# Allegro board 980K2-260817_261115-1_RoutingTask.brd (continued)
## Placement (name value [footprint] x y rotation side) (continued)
NOREF#2374  -  []  249.52 212.86 90 top
NOREF#2375  -  []  227.43 218.27 90 top
NOREF#2376  -  []  239.27 211.67 0 top
NOREF#2377  -  []  144.04 245.96 0 top
NOREF#2378  -  []  188.78 222.65 0 top
NOREF#2379  -  []  181.85 306.46 0 top
NOREF#2380  -  []  143.49 253.03 90 top
NOREF#2381  -  []  269.12 240.3 90 top
NOREF#2382  -  []  211.05 292.28 90 top
NOREF#2383  -  []  187.43 224.11 0 top
NOREF#2384  -  []  157.04 184.35 0 top
NOREF#2385  -  []  221.03 207.69 90 top
NOREF#2386  -  []  197.25 256.75 0 top
NOREF#2387  -  []  216.38 264.09 90 top
NOREF#2388  -  []  271.18 179.15 0 top
NOREF#2389  -  []  159.27 204.78 90 top
NOREF#2390  -  []  139.73 178.35 0 top
NOREF#2391  -  []  159.4 205.9 0 top
NOREF#2392  -  []  268.35 217.95 90 top
NOREF#2393  -  []  230.6 233.69 90 top
NOREF#2394  -  []  246.32 214.76 0 top
NOREF#2395  -  []  150.97 190.88 90 top
NOREF#2396  -  []  246.32 209.17 0 top
NOREF#2397  -  []  227.8 205.39 90 top
NOREF#2398  -  []  171.05 245.49 90 top
NOREF#2399  -  []  235.05 283.39 0 top
NOREF#2400  -  []  246.73 82.65 0 top
NOREF#2401  -  []  89.74 135.6 0 top
NOREF#2402  -  []  196.1 211.85 90 top
NOREF#2403  -  []  243.97 272 0 top
NOREF#2404  -  []  273.6 282.39 0 top
NOREF#2405  -  []  203.84 214.21 0 top
NOREF#2406  -  []  264.26 456.29 90 top
NOREF#2407  -  []  195.17 272.17 90 top
NOREF#2408  -  []  257.29 247.78 0 top
NOREF#2409  -  []  135.15 268.04 0 top
NOREF#2410  -  []  277.5 185.31 90 top
NOREF#2411  -  []  276.45 187.71 0 top
NOREF#2412  -  []  147.8 204.99 90 top
NOREF#2413  -  []  151.98 220.75 90 top
NOREF#2414  -  []  256.38 264.09 90 top
NOREF#2415  -  []  150.98 184.35 0 top
NOREF#2416  -  []  141.6 234.15 0 top
NOREF#2417  -  []  270.15 206.89 90 top
NOREF#2418  -  []  267.77 252.78 0 top
NOREF#2419  -  []  256.63 292.23 0 top
NOREF#2420  -  []  221.55 209.94 90 top
NOREF#2421  -  []  173.45 244.35 0 top
NOREF#2422  -  []  174.09 204.23 90 top
NOREF#2423  -  []  233.27 198.18 0 top
NOREF#2424  -  []  279.4 268.95 0 top
NOREF#2425  -  []  188.78 282.65 0 top
NOREF#2426  -  []  187.99 238.35 0 top
NOREF#2427  -  []  241.75 272.22 0 top
NOREF#2428  -  []  196.57 258.18 0 top
NOREF#2429  -  []  152.13 280.09 0 top
NOREF#2430  -  []  220.95 264.09 90 top
NOREF#2431  -  []  154.63 279.22 90 top
NOREF#2432  -  []  187.8 264.99 90 top
NOREF#2433  -  []  272.66 226.35 90 top
NOREF#2434  -  []  229.84 279.54 0 top
NOREF#2435  -  []  273.6 222.39 0 top
NOREF#2436  -  []  209.55 237.49 0 top
NOREF#2437  -  []  14.6 372.12 0 top
NOREF#2438  -  []  232.63 233.69 0 top
NOREF#2439  -  []  283.84 260.97 90 top
NOREF#2440  -  []  279.4 267.5 90 top
NOREF#2441  -  []  86.61 153.16 0 top
NOREF#2442  -  []  164.32 231.95 90 top
NOREF#2443  -  []  266.28 197.85 90 top
NOREF#2444  -  []  241.12 248.11 90 top
NOREF#2445  -  []  154.33 207.37 90 top
NOREF#2446  -  []  276.7 193.03 90 top
NOREF#2447  -  []  193.18 244.35 0 top
NOREF#2448  -  []  232.63 173.69 0 top
NOREF#2449  -  []  203.97 270.55 90 top
NOREF#2450  -  []  232.13 214.25 0 top
NOREF#2451  -  []  210.92 231.95 90 top
NOREF#2452  -  []  252.55 250.49 90 top
NOREF#2453  -  []  154.07 251.6 90 top
NOREF#2454  -  []  143.36 198.18 0 top
NOREF#2455  -  []  228.78 228.49 0 top
NOREF#2456  -  []  235.58 202.67 90 top
NOREF#2457  -  []  207.04 239.09 0 top
NOREF#2458  -  []  267.45 269.24 0 top
NOREF#2459  -  []  147.43 224.11 90 top
NOREF#2460  -  []  271.24 253.03 90 top
NOREF#2461  -  []  140.83 263.76 90 top
NOREF#2462  -  []  168.42 267.82 90 top
NOREF#2463  -  []  261.55 265.11 90 top
NOREF#2464  -  []  221.55 267.14 90 top
NOREF#2465  -  []  190.97 250.88 90 top
NOREF#2466  -  []  228.32 242.05 0 top
NOREF#2467  -  []  156.1 276.42 90 top
NOREF#2468  -  []  147.3 220.35 0 top
NOREF#2469  -  []  151.71 231.3 0 top
NOREF#2470  -  []  269.72 226.19 0 top
NOREF#2471  -  []  269.84 284.11 0 top
NOREF#2472  -  []  223.89 185.24 90 top
NOREF#2473  -  []  279.22 179.57 90 top
NOREF#2474  -  []  201.75 206.13 0 top
NOREF#2475  -  []  274.78 236.5 90 top
NOREF#2476  -  []  230.41 168.7 90 top
NOREF#2477  -  []  186.01 255.7 90 top
NOREF#2478  -  []  277.74 166.36 90 top
NOREF#2479  -  []  147.77 192.78 0 top
NOREF#2480  -  []  177.25 176.5 90 top
NOREF#2481  -  []  204.61 294.89 90 top
NOREF#2482  -  []  186.43 282.49 90 top
NOREF#2483  -  []  203.84 274.21 0 top
NOREF#2484  -  []  241.75 202.32 0 top
NOREF#2485  -  []  223.49 187.06 90 top
NOREF#2486  -  []  174.09 264.23 90 top
NOREF#2487  -  []  228.32 193.35 0 top
NOREF#2488  -  []  130.02 214.45 0 top
NOREF#2489  -  []  261.59 308.11 0 top
NOREF#2490  -  []  162.2 238.35 0 top
NOREF#2491  -  []  219.08 205.79 0 top
NOREF#2492  -  []  258.35 204.47 0 top
NOREF#2493  -  []  191.87 396.29 0 top
NOREF#2494  -  []  260.83 208.59 90 top
NOREF#2495  -  []  143.36 187.38 0 top
NOREF#2496  -  []  276.79 231.3 0 top
NOREF#2497  -  []  273.83 232.21 90 top
NOREF#2498  -  []  244.76 392.33 90 top
NOREF#2499  -  []  208.42 265.58 0 top
NOREF#2500  -  []  267.43 278.27 0 top
NOREF#2501  -  []  164.64 181.15 90 top
NOREF#2502  -  []  190.77 213.37 90 top
NOREF#2503  -  []  283.84 210.87 90 top
NOREF#2504  -  []  272.13 224.66 0 top
NOREF#2505  -  []  199.4 272 0 top
NOREF#2506  -  []  144.16 256.43 90 top
NOREF#2507  -  []  255.84 262.57 90 top
NOREF#2508  -  []  287.25 19.69 90 top
NOREF#2509  -  []  195.17 212.18 0 top
NOREF#2510  -  []  203.1 18.69 90 top
NOREF#2511  -  []  227.99 238.35 0 top
NOREF#2512  -  []  263.36 187.38 0 top
NOREF#2513  -  []  272.25 212.18 90 top
NOREF#2514  -  []  191.71 231.3 0 top
NOREF#2515  -  []  147.77 181.47 0 top
NOREF#2516  -  []  157.37 240.3 90 top
NOREF#2517  -  []  248.54 207.5 90 top
NOREF#2518  -  []  271.79 256.75 0 top
NOREF#2519  -  []  232.63 233.69 90 top
NOREF#2520  -  []  232.11 171.4 0 top
NOREF#2521  -  []  264.04 251.93 0 top
NOREF#2522  -  []  127.98 226.38 90 top
NOREF#2523  -  []  143.36 253.35 0 top
NOREF#2524  -  []  78.11 0 90 top
NOREF#2525  -  []  194.33 264.33 90 top
NOREF#2526  -  []  193.18 277.69 90 top
NOREF#2527  -  []  251.21 234.89 90 top
NOREF#2528  -  []  193.18 211.85 90 top
NOREF#2529  -  []  191.79 196.75 0 top
NOREF#2530  -  []  211.05 232.28 90 top
NOREF#2531  -  []  190.15 266.89 90 top
NOREF#2532  -  []  192.63 233.69 90 top
NOREF#2533  -  []  148.44 257.85 90 top
NOREF#2534  -  []  196.02 257.6 0 top
NOREF#2535  -  []  174.09 267.27 90 top
NOREF#2536  -  []  288.42 204.78 90 top
NOREF#2537  -  []  275.17 276.75 90 top
NOREF#2538  -  []  230.48 235.77 0 top
NOREF#2539  -  []  151.24 193.03 90 top
NOREF#2540  -  []  149.72 281.62 0 top
NOREF#2541  -  []  133.64 239.09 0 top
NOREF#2542  -  []  259.08 203.76 0 top
NOREF#2543  -  []  193.95 256.75 0 top
NOREF#2544  -  []  271.53 233.37 90 top
NOREF#2545  -  []  225.41 273.02 90 top
NOREF#2546  -  []  176.83 287.03 0 top
NOREF#2547  -  []  163.4 236.38 0 top
NOREF#2548  -  []  201.75 274.76 0 top
NOREF#2549  -  []  148.44 197.85 90 top
NOREF#2550  -  []  239.4 274.54 0 top
NOREF#2551  -  []  146.43 222.5 90 top
NOREF#2552  -  []  189.12 196.43 90 top
NOREF#2553  -  []  240.23 236.17 90 top
NOREF#2554  -  []  152.63 233.69 90 top
NOREF#2555  -  []  131.22 234.24 90 top
NOREF#2556  -  []  235.15 176.17 90 top
NOREF#2557  -  []  147.8 264.99 90 top
NOREF#2558  -  []  91.03 127.87 0 top
NOREF#2559  -  []  263.49 187.06 90 top
NOREF#2560  -  []  84.45 359.42 0 top
NOREF#2561  -  []  184.04 191.93 0 top
NOREF#2562  -  []  243.84 208.62 0 top
NOREF#2563  -  []  140.83 205.79 90 top
NOREF#2564  -  []  212.55 284.49 0 top
NOREF#2565  -  []  204.32 231.95 90 top
NOREF#2566  -  []  140.83 268.59 90 top
NOREF#2567  -  []  163.97 212 0 top
NOREF#2568  -  []  188.99 191.93 0 top
NOREF#2569  -  []  236.61 233.37 90 top
NOREF#2570  -  []  196.81 232.54 0 top
NOREF#2571  -  []  224.04 185.96 0 top
NOREF#2572  -  []  124.55 148.49 90 top
NOREF#2573  -  []  125.25 291.4 0 top
NOREF#2574  -  []  208.54 207.5 90 top
NOREF#2575  -  []  192.25 278.02 90 top
NOREF#2576  -  []  273.27 193.35 0 top
NOREF#2577  -  []  227.9 265.84 90 top
NOREF#2578  -  []  153.95 256.75 0 top
NOREF#2579  -  []  205.04 293.3 90 top
NOREF#2580  -  []  190.56 252.78 0 top
NOREF#2581  -  []  151.7 277.85 0 top
NOREF#2582  -  []  149.21 17.15 0 top
NOREF#2583  -  []  265.09 257.49 90 top
NOREF#2584  -  []  239.27 270.87 90 top
NOREF#2585  -  []  162.88 458.49 0 top
NOREF#2586  -  []  182.81 197.6 0 top
NOREF#2587  -  []  140.95 268.91 90 top
NOREF#2588  -  []  188.78 228.49 0 top
NOREF#2589  -  []  188.81 255.7 90 top
NOREF#2590  -  []  94.87 108.59 0 top
NOREF#2591  -  []  163.84 274.21 0 top
NOREF#2592  -  []  243.84 260.97 90 top
NOREF#2593  -  []  214.43 292.23 0 top
NOREF#2594  -  []  219.55 234.49 0 top
NOREF#2595  -  []  152.11 231.4 0 top
NOREF#2596  -  []  199.27 264.78 90 top
NOREF#2597  -  []  86.61 132.84 0 top
NOREF#2598  -  []  228.35 217.95 90 top
NOREF#2599  -  []  235.56 235.77 0 top
NOREF#2600  -  []  269.84 273.7 90 top
NOREF#2601  -  []  181.55 205.11 90 top
NOREF#2602  -  []  154.78 176.5 90 top
NOREF#2603  -  []  239.72 279.22 90 top
NOREF#2604  -  []  196.57 193.35 0 top
NOREF#2605  -  []  231.11 198.18 0 top
NOREF#2606  -  []  183.36 193.35 0 top
NOREF#2607  -  []  154.63 282.42 0 top
NOREF#2608  -  []  231.98 280.75 90 top
NOREF#2609  -  []  264.24 20.69 90 top
NOREF#2610  -  []  151.19 228.49 0 top
NOREF#2611  -  []  136.5 271.94 0 top
NOREF#2612  -  []  144.04 191.93 0 top
NOREF#2613  -  []  122.57 231.95 0 top
NOREF#2614  -  []  188.78 244.35 0 top
NOREF#2615  -  []  151.79 256.75 0 top
NOREF#2616  -  []  241.84 295.2 0 top
NOREF#2617  -  []  236.7 253.03 90 top
NOREF#2618  -  []  175.11 201.22 90 top
NOREF#2619  -  []  229.84 279.54 90 top
NOREF#2620  -  []  272.25 218.02 90 top
NOREF#2621  -  []  283.97 207.5 90 top
NOREF#2622  -  []  249.52 200.42 90 top
NOREF#2623  -  []  174.07 210.89 90 top
NOREF#2624  -  []  221.55 265.11 90 top
NOREF#2625  -  []  159.65 212.56 0 top
NOREF#2626  -  []  194.39 222.02 90 top
NOREF#2627  -  []  241.75 266.13 0 top
NOREF#2628  -  []  274.39 216.17 90 top
NOREF#2629  -  []  269.72 221.62 0 top
NOREF#2630  -  []  259.08 205.79 0 top
NOREF#2631  -  []  272.25 222.59 90 top
NOREF#2632  -  []  146.17 212.17 90 top
NOREF#2633  -  []  164.04 237.5 90 top
NOREF#2634  -  []  125.08 17.15 0 top
NOREF#2635  -  []  185.41 286.99 90 top
NOREF#2636  -  []  153.76 190.88 90 top
NOREF#2637  -  []  186.16 200.17 90 top
NOREF#2638  -  []  170.92 231.95 90 top
NOREF#2639  -  []  218.97 211.91 90 top
NOREF#2640  -  []  232.25 272.17 90 top
NOREF#2641  -  []  159.44 179.15 0 top
NOREF#2642  -  []  254.09 207.27 90 top
NOREF#2643  -  []  152.13 214.25 0 top
NOREF#2644  -  []  239.27 205.58 0 top
NOREF#2645  -  []  157.03 178.07 0 top
NOREF#2646  -  []  159.24 244.35 0 top
NOREF#2647  -  []  239.4 210.55 90 top
NOREF#2648  -  []  273.18 184.35 0 top
NOREF#2649  -  []  266.01 190.88 90 top
NOREF#2650  -  []  243.4 296.38 0 top
NOREF#2651  -  []  149.12 256.43 90 top
NOREF#2652  -  []  235.17 221.32 0 top
NOREF#2653  -  []  196.52 225.69 0 top
NOREF#2654  -  []  237.74 166.36 90 top
NOREF#2655  -  []  177.25 236.5 90 top
NOREF#2656  -  []  192.72 257.6 0 top
NOREF#2657  -  []  163.97 208.95 0 top
NOREF#2658  -  []  279.22 250.88 90 top
NOREF#2659  -  []  208.54 202.09 0 top
NOREF#2660  -  []  187.3 220.35 0 top
NOREF#2661  -  []  190.97 179.57 90 top
NOREF#2662  -  []  243.97 270.55 90 top
NOREF#2663  -  []  276.57 193.35 0 top
NOREF#2664  -  []  254.38 264.09 0 top
NOREF#2665  -  []  266.69 223.05 90 top
NOREF#2666  -  []  209.55 237.49 0 top
NOREF#2667  -  []  203.84 261.77 0 top
NOREF#2668  -  []  276.57 198.18 0 top
NOREF#2669  -  []  146.17 286.14 90 top
NOREF#2670  -  []  275.56 235.77 0 top
NOREF#2671  -  []  133.36 261.22 0 top
NOREF#2672  -  []  235.92 195.7 90 top
NOREF#2673  -  []  152.25 282.59 90 top
NOREF#2674  -  []  246.32 206.13 0 top
NOREF#2675  -  []  187.8 205.39 90 top
NOREF#2676  -  []  196.45 247.71 0 top
NOREF#2677  -  []  222.87 213.02 0 top
NOREF#2678  -  []  252.87 287.4 90 top
NOREF#2679  -  []  178.35 267.01 0 top
NOREF#2680  -  []  174.07 270.89 90 top
NOREF#2681  -  []  188.81 250.88 90 top
NOREF#2682  -  []  199.27 205.58 0 top
NOREF#2683  -  []  268.35 277.95 90 top
NOREF#2684  -  []  196.1 271.85 90 top
NOREF#2685  -  []  157.71 233.69 0 top
NOREF#2686  -  []  254.38 204.09 0 top
NOREF#2687  -  []  187.77 192.78 0 top
NOREF#2688  -  []  237.71 172.86 0 top
NOREF#2689  -  []  264.16 256.43 90 top
NOREF#2690  -  []  209.52 204.23 90 top
NOREF#2691  -  []  283.84 268.62 0 top
NOREF#2692  -  []  198.91 232.21 90 top
NOREF#2693  -  []  159.27 201.77 0 top
NOREF#2694  -  []  235.68 173.69 90 top
NOREF#2695  -  []  275.56 175.77 0 top
NOREF#2696  -  []  151.7 274.65 90 top
NOREF#2697  -  []  197.92 190.01 0 top
NOREF#2698  -  []  227.45 209.24 0 top
NOREF#2699  -  []  283.84 264.78 90 top
NOREF#2700  -  []  237.37 180.3 90 top
NOREF#2701  -  []  174.34 82.65 0 top
NOREF#2702  -  []  248.42 208.62 0 top
NOREF#2703  -  []  266.16 212.17 90 top
NOREF#2704  -  []  136.38 264.09 90 top
NOREF#2705  -  []  197.71 173.69 0 top
NOREF#2706  -  []  259.55 240.49 90 top
NOREF#2707  -  []  156.61 173.37 90 top
NOREF#2708  -  []  249.17 291.95 0 top
NOREF#2709  -  []  164.95 260.42 90 top
NOREF#2710  -  []  274.39 286.59 90 top
NOREF#2711  -  []  136.38 204.09 90 top
NOREF#2712  -  []  233.76 195.7 90 top
NOREF#2713  -  []  151.76 167.33 0 top
NOREF#2714  -  []  267.77 257.6 0 top
NOREF#2715  -  []  172.55 284.49 0 top
NOREF#2716  -  []  165.49 452.29 90 top
NOREF#2717  -  []  218.83 292.23 0 top
NOREF#2718  -  []  233.6 286.96 0 top
NOREF#2719  -  []  167.95 226.12 90 top
NOREF#2720  -  []  153.6 222.39 0 top
NOREF#2721  -  []  215.84 202.57 90 top
NOREF#2722  -  []  163.84 204.78 90 top
NOREF#2723  -  []  233.18 271.85 90 top
NOREF#2724  -  []  264.26 396.29 0 top
NOREF#2725  -  []  232.51 175.77 0 top
NOREF#2726  -  []  286.32 202.32 0 top
NOREF#2727  -  []  183.49 187.06 90 top
NOREF#2728  -  []  131.05 245.49 90 top
NOREF#2729  -  []  209.52 207.27 90 top
NOREF#2730  -  []  159.22 179.57 90 top
NOREF#2731  -  []  265.42 214.72 90 top
NOREF#2732  -  []  195.05 278.82 0 top
NOREF#2733  -  []  147.43 218.27 0 top
NOREF#2734  -  []  184.04 245.96 0 top
NOREF#2735  -  []  155.96 228.6 90 top
NOREF#2736  -  []  284.95 267.27 90 top
NOREF#2737  -  []  235.17 221.32 90 top
NOREF#2738  -  []  251.05 289.49 0 top
NOREF#2739  -  []  228.78 184.35 0 top
NOREF#2740  -  []  134.38 264.09 0 top
NOREF#2741  -  []  244.32 291.95 90 top
NOREF#2742  -  []  202.44 232.28 0 top
NOREF#2743  -  []  142.81 241.71 0 top
NOREF#2744  -  []  197.04 184.35 0 top
NOREF#2745  -  []  188.99 256.75 0 top
NOREF#2746  -  []  136.5 285.91 0 top
NOREF#2747  -  []  185.61 257.6 0 top
NOREF#2748  -  []  228.32 185.63 90 top
NOREF#2749  -  []  231.11 260.17 90 top
NOREF#2750  -  []  221.55 205.11 90 top
NOREF#2751  -  []  269.84 219.54 90 top
NOREF#2752  -  []  171.22 234.24 90 top
NOREF#2753  -  []  148.35 217.95 90 top
NOREF#2754  -  []  199.24 244.35 0 top
NOREF#2755  -  []  125.25 291.4 90 top
NOREF#2756  -  []  164.95 267.27 90 top
NOREF#2757  -  []  162.85 297.22 0 top
NOREF#2758  -  []  213.65 239.15 0 top
NOREF#2759  -  []  245.38 226.23 0 top
NOREF#2760  -  []  243.84 271.67 0 top
NOREF#2761  -  []  326.72 389.27 90 top
NOREF#2762  -  []  144.71 241.71 90 top
NOREF#2763  -  []  157.74 226.35 90 top
NOREF#2764  -  []  191.19 283.92 0 top
NOREF#2765  -  []  148.32 193.35 0 top
NOREF#2766  -  []  268.35 283.79 90 top
NOREF#2767  -  []  89.76 165.64 0 top
NOREF#2768  -  []  199.27 261.77 0 top
NOREF#2769  -  []  275.17 276.75 0 top
NOREF#2770  -  []  206.32 214.76 0 top
NOREF#2771  -  []  276.8 280.49 90 top
NOREF#2772  -  []  257.25 236.5 90 top
NOREF#2773  -  []  213.62 229.09 90 top
NOREF#2774  -  []  187.99 178.35 0 top
NOREF#2775  -  []  88.44 105.03 90 top
NOREF#2776  -  []  276.54 167 0 top
NOREF#2777  -  []  233.39 193.03 90 top
NOREF#2778  -  []  208.94 221.73 0 top
NOREF#2779  -  []  204.95 204.23 90 top
NOREF#2780  -  []  229.84 284.11 0 top
NOREF#2781  -  []  188.99 180.62 0 top
NOREF#2782  -  []  159.4 210.55 90 top
NOREF#2783  -  []  135.11 261.22 90 top
NOREF#2784  -  []  241.75 274.76 0 top
NOREF#2785  -  []  179.08 205.79 0 top
NOREF#2786  -  []  165.38 286.23 0 top
NOREF#2787  -  []  249.49 220.89 0 top
NOREF#2788  -  []  189.12 251.6 90 top
NOREF#2789  -  []  275.96 228.6 90 top
NOREF#2790  -  []  268.95 266.89 0 top
NOREF#2791  -  []  264.26 456.29 0 top
NOREF#2792  -  []  157.37 251.6 90 top
NOREF#2793  -  []  283.97 265.9 0 top
NOREF#2794  -  []  251.36 18.69 90 top
NOREF#2795  -  []  156.57 185.63 0 top
NOREF#2796  -  []  230.77 223.79 90 top
NOREF#2797  -  []  239.4 204.45 90 top
NOREF#2798  -  []  279.72 223.79 90 top
NOREF#2799  -  []  136.63 232.23 0 top
NOREF#2800  -  []  250.89 269.17 0 top
NOREF#2801  -  []  188.44 241.72 90 top
NOREF#2802  -  []  187.43 278.27 90 top
NOREF#2803  -  []  180.83 205.79 90 top
NOREF#2804  -  []  194.39 282.02 90 top
NOREF#2805  -  []  191.11 198.18 0 top
NOREF#2806  -  []  186.16 253.35 0 top
NOREF#2807  -  []  266.43 236.47 90 top
NOREF#2808  -  []  150.48 175.77 0 top
NOREF#2809  -  []  220.83 205.79 90 top
NOREF#2810  -  []  178.95 268.91 0 top
NOREF#2811  -  []  190.73 19.69 90 top
NOREF#2812  -  []  176.55 254.49 90 top
NOREF#2813  -  []  268.78 228.49 0 top
NOREF#2814  -  []  260.83 205.79 90 top
NOREF#2815  -  []  134.43 232.23 0 top
NOREF#2816  -  []  178.95 204.09 0 top
NOREF#2817  -  []  190.97 255.7 90 top
NOREF#2818  -  []  152.25 272.17 0 top
NOREF#2819  -  []  80.49 135.25 0 top
NOREF#2820  -  []  154.33 264.33 90 top
NOREF#2821  -  []  267.43 284.11 0 top
NOREF#2822  -  []  197.47 17.15 90 top
NOREF#2823  -  []  157.59 235.77 0 top
NOREF#2824  -  []  164.61 294.89 90 top
NOREF#2825  -  []  163.97 274.54 0 top
NOREF#2826  -  []  149.29 279.37 0 top
NOREF#2827  -  []  151.7 280.49 90 top
NOREF#2828  -  []  88.14 151.13 90 top
NOREF#2829  -  []  270.88 168.6 90 top
NOREF#2830  -  []  196.57 242.05 0 top
NOREF#2831  -  []  210.02 274.45 0 top
NOREF#2832  -  []  196.84 227.33 0 top
NOREF#2833  -  []  260.95 201.55 90 top
NOREF#2834  -  []  144.16 251.6 90 top
NOREF#2835  -  []  181.85 292.49 0 top
NOREF#2836  -  []  267.03 231.4 0 top
NOREF#2837  -  []  189.84 284.11 90 top
NOREF#2838  -  []  215.24 201.55 90 top
NOREF#2839  -  []  267.8 264.99 90 top
NOREF#2840  -  []  267.3 286.19 0 top
NOREF#2841  -  []  169.05 232.28 0 top
NOREF#2842  -  []  225.41 226.99 90 top
NOREF#2843  -  []  196.33 227.9 90 top
NOREF#2844  -  []  235.92 250.88 90 top
NOREF#2845  -  []  213.65 179.15 0 top
NOREF#2846  -  []  169.52 204.23 90 top
NOREF#2847  -  []  197.37 191.6 90 top
NOREF#2848  -  []  276.52 285.69 0 top
NOREF#2849  -  []  250.89 266.13 0 top
NOREF#2850  -  []  283.84 208.62 0 top
NOREF#2851  -  []  196.57 185.63 0 top
NOREF#2852  -  []  168.42 205.58 0 top
NOREF#2853  -  []  284.95 212.86 90 top
NOREF#2854  -  []  187.3 286.19 0 top
NOREF#2855  -  []  196.54 227 0 top
NOREF#2856  -  []  187.8 204.99 90 top
NOREF#2857  -  []  237.25 180.62 0 top
NOREF#2858  -  []  231.95 178.07 0 top
NOREF#2859  -  []  249.49 280.89 0 top
NOREF#2860  -  []  133.24 201.55 0 top
NOREF#2861  -  []  197.74 166.36 90 top
NOREF#2862  -  []  279.44 179.15 0 top
NOREF#2863  -  []  203.84 271.67 0 top
NOREF#2864  -  []  193.18 217.69 90 top
NOREF#2865  -  []  254.43 232.23 0 top
NOREF#2866  -  []  164.95 204.23 90 top
NOREF#2867  -  []  149.84 284.11 0 top
NOREF#2868  -  []  188.32 253.35 0 top
NOREF#2869  -  []  154.51 259.27 90 top
NOREF#2870  -  []  288.42 265.58 0 top
NOREF#2871  -  []  203.97 268.95 0 top
NOREF#2872  -  []  193.03 172.1 0 top
NOREF#2873  -  []  227.77 181.47 0 top
NOREF#2874  -  []  138.35 209.04 0 top
NOREF#2875  -  []  171.05 292.28 90 top
NOREF#2876  -  []  146.88 286.59 90 top
NOREF#2877  -  []  267.77 192.78 0 top
NOREF#2878  -  []  208.54 205.9 0 top
NOREF#2879  -  []  229.12 191.6 90 top
NOREF#2880  -  []  276.52 225.69 0 top
NOREF#2881  -  []  211.65 233.3 90 top
NOREF#2882  -  []  203.04 176.5 90 top
NOREF#2883  -  []  199.72 219.22 90 top
NOREF#2884  -  []  265.41 226.99 90 top
NOREF#2885  -  []  231.71 231.3 0 top
NOREF#2886  -  []  256.63 232.23 0 top
NOREF#2887  -  []  227.03 171.4 0 top
NOREF#2888  -  []  138.83 232.23 0 top
NOREF#2889  -  []  244.95 272.86 90 top
NOREF#2890  -  []  244.64 181.15 90 top
NOREF#2891  -  []  243.97 265.9 0 top
NOREF#2892  -  []  150.77 219.22 90 top
NOREF#2893  -  []  156.02 236.37 0 top
NOREF#2894  -  []  219.73 238.35 0 top
NOREF#2895  -  []  187.03 231.4 0 top
NOREF#2896  -  []  159.4 204.45 90 top
NOREF#2897  -  []  238.99 19.69 90 top
NOREF#2898  -  []  146.28 193.03 90 top
NOREF#2899  -  []  132.64 204.47 0 top
NOREF#2900  -  []  159.4 207.5 90 top
NOREF#2901  -  []  193.6 222.39 0 top
NOREF#2902  -  []  190.48 175.77 0 top
NOREF#2903  -  []  130.58 263.21 0 top
NOREF#2904  -  []  218.85 241.15 90 top
NOREF#2905  -  []  197.18 176.17 90 top
NOREF#2906  -  []  201.41 167.9 90 top
NOREF#2907  -  []  289.52 260.42 90 top
NOREF#2908  -  []  190.6 173.69 90 top
NOREF#2909  -  []  279.4 205.9 0 top
NOREF#2910  -  []  278.91 232.21 90 top
NOREF#2911  -  []  228.44 193.03 90 top
NOREF#2912  -  []  176.83 227.03 0 top
NOREF#2913  -  []  132.87 287.4 90 top
NOREF#2914  -  []  151.7 288.26 0 top
NOREF#2915  -  []  227.03 231.4 0 top
NOREF#2916  -  []  209.87 389.27 90 top
NOREF#2917  -  []  248.42 260.97 90 top
NOREF#2918  -  []  239.06 238.07 0 top
NOREF#2919  -  []  288.39 456.29 90 top
NOREF#2920  -  []  275.68 173.69 90 top
NOREF#2921  -  []  268.32 193.35 0 top
NOREF#2922  -  []  272.13 214.25 0 top
NOREF#2923  -  []  199.24 184.35 0 top
NOREF#2924  -  []  197.04 184.35 0 top
NOREF#2925  -  []  155.17 281.32 0 top
NOREF#2926  -  []  272.13 284.66 0 top
NOREF#2927  -  []  171.25 244.35 0 top
NOREF#2928  -  []  243.84 213.41 90 top
NOREF#2929  -  []  149.21 17.15 90 top
NOREF#2930  -  []  94.87 102.74 90 top
NOREF#2931  -  []  202.57 291.95 0 top
NOREF#2932  -  []  199.27 210.87 90 top
NOREF#2933  -  []  258.85 241.15 90 top
NOREF#2934  -  []  186.96 251.6 90 top
NOREF#2935  -  []  228.44 197.85 90 top
NOREF#2936  -  []  239.27 213.41 90 top
NOREF#2937  -  []  163.84 207.82 90 top
NOREF#2938  -  []  150.63 259.3 0 top
NOREF#2939  -  []  173.78 267.01 0 top
NOREF#2940  -  []  139.73 178.35 0 top
NOREF#2941  -  []  231.24 197.85 90 top
NOREF#2942  -  []  312.5 18.69 90 top
NOREF#2943  -  []  191.53 173.37 90 top
NOREF#2944  -  []  236.57 242.05 0 top
NOREF#2945  -  []  265.61 192.78 0 top
NOREF#2946  -  []  281.75 262.32 0 top
NOREF#2947  -  []  192.51 175.77 0 top
NOREF#2948  -  []  239.4 207.5 90 top
NOREF#2949  -  []  157.37 256.43 90 top
NOREF#2950  -  []  155.17 281.32 90 top
NOREF#2951  -  []  246.32 269.17 0 top
NOREF#2952  -  []  247.04 239.09 0 top
NOREF#2953  -  []  256.55 194.49 90 top
NOREF#2954  -  []  199.4 264.45 90 top
NOREF#2955  -  []  162.44 292.28 0 top
NOREF#2956  -  []  183.36 258.18 0 top
NOREF#2957  -  []  258.95 268.91 0 top
NOREF#2958  -  []  232.13 274.25 0 top
NOREF#2959  -  []  281.75 209.17 0 top
NOREF#2960  -  []  142.88 286.99 0 top
NOREF#2961  -  []  197.37 240.3 90 top
NOREF#2962  -  []  294.09 207.27 90 top
NOREF#2963  -  []  234.07 251.6 90 top
NOREF#2964  -  []  277.74 226.35 90 top
NOREF#2965  -  []  283.97 200.64 90 top
NOREF#2966  -  []  159.27 208.62 0 top
NOREF#2967  -  []  190.56 192.78 0 top
NOREF#2968  -  []  161.41 227.9 90 top
NOREF#2969  -  []  256.55 280.49 0 top
NOREF#2970  -  []  259.55 180.49 90 top
NOREF#2971  -  []  147.8 209.99 0 top
NOREF#2972  -  []  131.05 229.49 0 top
NOREF#2973  -  []  95.33 20.69 90 top
NOREF#2974  -  []  228.35 283.79 90 top
NOREF#2975  -  []  277.92 250.01 0 top
NOREF#2976  -  []  232.72 197.6 0 top
NOREF#2977  -  []  218.35 209.04 0 top
NOREF#2978  -  []  158.04 228.3 0 top
NOREF#2979  -  []  186.83 196.75 0 top
NOREF#2980  -  []  276.1 216.42 90 top
NOREF#2981  -  []  198.11 172.1 0 top
NOREF#2982  -  []  193.18 282.26 90 top
NOREF#2983  -  []  146.88 280.75 90 top
NOREF#2984  -  []  239.22 255.7 90 top
NOREF#2985  -  []  159.4 214.54 0 top
NOREF#2986  -  []  186.16 272.17 90 top
NOREF#2987  -  []  242.26 236.17 90 top
NOREF#2988  -  []  235.05 218.82 0 top
NOREF#2989  -  []  153.6 216.55 0 top
NOREF#2990  -  []  178.35 264.47 0 top
NOREF#2991  -  []  227.3 220.35 0 top
NOREF#2992  -  []  283.97 214.54 0 top
NOREF#2993  -  []  189.84 224.11 90 top
NOREF#2994  -  []  106.68 148.34 0 top
NOREF#2995  -  []  223.36 247.38 0 top
NOREF#2996  -  []  190.77 273.37 90 top
NOREF#2997  -  []  180.43 284.38 90 top
NOREF#2998  -  []  148.78 244.35 0 top
NOREF#2999  -  []  264.16 245.63 90 top
NOREF#3000  -  []  269.24 245.31 90 top
NOREF#3001  -  []  284.95 204.23 90 top
NOREF#3002  -  []  288.54 208.95 0 top
NOREF#3003  -  []  231.79 191.93 0 top
NOREF#3004  -  []  196.1 216.42 90 top
NOREF#3005  -  []  135.15 265.24 0 top
NOREF#3006  -  []  179.73 238.35 0 top
NOREF#3007  -  []  181.55 207.14 90 top
NOREF#3008  -  []  188.44 197.85 90 top
NOREF#3009  -  []  273.94 196.75 0 top
NOREF#3010  -  []  203.84 267.82 90 top
NOREF#3011  -  []  228.32 198.18 0 top
NOREF#3012  -  []  262.87 273.02 0 top
NOREF#3013  -  []  251.25 184.35 0 top
NOREF#3014  -  []  223.36 193.35 0 top
NOREF#3015  -  []  236.8 274.65 90 top
NOREF#3016  -  []  159.22 190.88 90 top
NOREF#3017  -  []  248.45 295.2 0 top
NOREF#3018  -  []  159.06 238.07 0 top
NOREF#3019  -  []  283.97 260.64 90 top
NOREF#3020  -  []  104.35 456.29 0 top
NOREF#3021  -  []  279.27 208.62 0 top
NOREF#3022  -  []  253.78 207.01 0 top
NOREF#3023  -  []  241.75 269.17 0 top
NOREF#3024  -  []  151.91 196.43 90 top
NOREF#3025  -  []  276.8 214.65 90 top
NOREF#3026  -  []  157.04 184.35 0 top
NOREF#3027  -  []  219.73 238.35 0 top
NOREF#3028  -  []  273.6 216.55 0 top
NOREF#3029  -  []  246.32 262.32 0 top
NOREF#3030  -  []  244.44 232.28 90 top
NOREF#3031  -  []  250.02 274.45 0 top
NOREF#3032  -  []  271.19 223.92 0 top
NOREF#3033  -  []  206.32 272.22 0 top
NOREF#3034  -  []  233.76 250.88 90 top
NOREF#3035  -  []  161.44 244.35 0 top
NOREF#3036  -  []  266.16 253.35 0 top
NOREF#3037  -  []  176.55 194.49 90 top
NOREF#3038  -  []  243.92 289.94 0 top
NOREF#3039  -  []  199.27 274.21 0 top
NOREF#3040  -  []  211.05 245.49 90 top
NOREF#3041  -  []  157.25 240.62 0 top
NOREF#3042  -  []  190.97 195.7 90 top
NOREF#3043  -  []  216.55 280.49 0 top
NOREF#3044  -  []  237.59 175.77 0 top
NOREF#3045  -  []  152.63 232.86 0 top
NOREF#3046  -  []  281.75 202.32 0 top
NOREF#3047  -  []  168.54 260.64 90 top
NOREF#3048  -  []  163.84 268.62 0 top
NOREF#3049  -  []  236.02 241.47 0 top
NOREF#3050  -  []  211.05 185.49 90 top
NOREF#3051  -  []  243.84 200.97 90 top
NOREF#3052  -  []  192.63 232.86 0 top
NOREF#3053  -  []  147.77 247.68 0 top
NOREF#3054  -  []  275.49 168.7 90 top
NOREF#3055  -  []  152.25 212.18 90 top
NOREF#3056  -  []  88.14 130.81 90 top
NOREF#3057  -  []  228.19 187.71 0 top
NOREF#3058  -  []  283.97 208.95 0 top
NOREF#3059  -  []  147.51 250.88 90 top
NOREF#3060  -  []  131.05 289.49 0 top
NOREF#3061  -  []  264.16 191.6 90 top
NOREF#3062  -  []  251.21 294.24 90 top
NOREF#3063  -  []  245.73 17.15 0 top
NOREF#3064  -  []  241.41 227.9 90 top
NOREF#3065  -  []  248.54 208.95 0 top
NOREF#3066  -  []  207.95 286.12 90 top
NOREF#3067  -  []  223.49 257.85 90 top
NOREF#3068  -  []  223.49 193.03 90 top
NOREF#3069  -  []  258.95 264.09 0 top
NOREF#3070  -  []  156.7 193.03 90 top
NOREF#3071  -  []  149.12 180.3 90 top
NOREF#3072  -  []  213.45 184.35 0 top
NOREF#3073  -  []  168.54 262.09 0 top
NOREF#3074  -  []  166.32 209.17 0 top
NOREF#3075  -  []  209.55 237.49 0 top
NOREF#3076  -  []  203.97 205.9 0 top
NOREF#3077  -  []  268.81 195.7 90 top
NOREF#3078  -  []  148.78 184.35 0 top
NOREF#3079  -  []  199.4 273.09 90 top
NOREF#3080  -  []  152.25 282.59 0 top
NOREF#3081  -  []  235.92 255.7 90 top
NOREF#3082  -  []  173.34 17.15 90 top
NOREF#3083  -  []  153.18 211.85 90 top
NOREF#3084  -  []  133.62 229.09 90 top
NOREF#3085  -  []  203.84 260.97 90 top
NOREF#3086  -  []  145.42 273.02 90 top
NOREF#3087  -  []  192.66 166.36 90 top
NOREF#3088  -  []  220.95 204.09 90 top
NOREF#3089  -  []  148.78 244.35 0 top
NOREF#3090  -  []  228.78 222.65 0 top
NOREF#3091  -  []  173.45 184.35 0 top
NOREF#3092  -  []  229.67 190.01 0 top
NOREF#3093  -  []  262.81 197.6 0 top
NOREF#3094  -  []  312.52 456.29 0 top
NOREF#3095  -  []  235.68 233.69 90 top
NOREF#3096  -  []  193.18 271.85 90 top
NOREF#3097  -  []  286.32 209.17 0 top
NOREF#3098  -  []  144.71 247.68 90 top
NOREF#3099  -  []  273.6 276.55 0 top
NOREF#3100  -  []  140.95 201.55 90 top
NOREF#3101  -  []  279.27 260.97 90 top
NOREF#3102  -  []  186.28 197.85 90 top
NOREF#3103  -  []  236.8 220.49 90 top
NOREF#3104  -  []  191.24 253.03 90 top
NOREF#3105  -  []  226.96 251.6 90 top
NOREF#3106  -  []  233.6 216.55 0 top
NOREF#3107  -  []  279.4 265.9 0 top
NOREF#3108  -  []  232.25 278.02 0 top
NOREF#3109  -  []  219.73 178.35 0 top
NOREF#3110  -  []  95.35 452.29 90 top
NOREF#3111  -  []  227.9 205.84 90 top
NOREF#3112  -  []  230.98 244.35 0 top
NOREF#3113  -  []  193.6 276.55 0 top
NOREF#3114  -  []  182.03 289.03 90 top
NOREF#3115  -  []  142.81 247.68 0 top
NOREF#3116  -  []  232.63 232.86 0 top
NOREF#3117  -  []  162.2 178.35 0 top
NOREF#3118  -  []  194.33 204.33 90 top
NOREF#3119  -  []  283.97 272 0 top
NOREF#3120  -  []  244.95 267.27 90 top
NOREF#3121  -  []  218.95 208.91 0 top
NOREF#3122  -  []  269.72 286.19 0 top
NOREF#3123  -  []  254.51 203.76 0 top
NOREF#3124  -  []  147.12 276.42 0 top
NOREF#3125  -  []  267.99 238.35 0 top
NOREF#3126  -  []  256.26 203.76 90 top
NOREF#3127  -  []  195.56 175.77 0 top
NOREF#3128  -  []  271.76 227.33 0 top
NOREF#3129  -  []  162.87 16.49 0 top
NOREF#3130  -  []  122.2 178.35 0 top
NOREF#3131  -  []  199.27 214.21 0 top
NOREF#3132  -  []  277.59 235.77 0 top
NOREF#3133  -  []  153.56 173.37 90 top
NOREF#3134  -  []  226.7 283.04 90 top
NOREF#3135  -  []  233.18 217.69 90 top
NOREF#3136  -  []  239.4 205.9 0 top
NOREF#3137  -  []  175.02 208.14 90 top
NOREF#3138  -  []  83.04 164.54 90 top
NOREF#3139  -  []  156.1 216.42 90 top
NOREF#3140  -  []  281.12 248.11 90 top
NOREF#3141  -  []  290.89 266.13 0 top
NOREF#3142  -  []  243.97 205.9 0 top
NOREF#3143  -  []  274.78 176.5 90 top
NOREF#3144  -  []  260.95 208.91 90 top
NOREF#3145  -  []  228.95 206.89 0 top
NOREF#3146  -  []  236.61 173.37 90 top
NOREF#3147  -  []  275.17 212.18 90 top
NOREF#3148  -  []  136.28 307.18 0 top
NOREF#3149  -  []  190.97 239.57 90 top
NOREF#3150  -  []  288.39 396.29 0 top
NOREF#3151  -  []  205.38 286.23 0 top
NOREF#3152  -  []  178.35 207.01 0 top
NOREF#3153  -  []  145.61 192.78 0 top
NOREF#3154  -  []  237.04 244.35 0 top
NOREF#3155  -  []  192.11 171.4 0 top
NOREF#3156  -  []  192.63 172.86 0 top
NOREF#3157  -  []  150.56 247.68 0 top
NOREF#3158  -  []  196.8 214.65 90 top
NOREF#3159  -  []  288.54 200.64 90 top
NOREF#3160  -  []  279.24 244.35 0 top
NOREF#3161  -  []  270.77 273.37 90 top
NOREF#3162  -  []  283.84 271.67 0 top
NOREF#3163  -  []  186.83 191.93 0 top
NOREF#3164  -  []  150.77 213.37 90 top
NOREF#3165  -  []  188.32 185.63 90 top
NOREF#3166  -  []  198.64 233.37 90 top
NOREF#3167  -  []  283.84 265.58 0 top
NOREF#3168  -  []  146.43 236.47 90 top
NOREF#3169  -  []  137.28 286.47 90 top
NOREF#3170  -  []  95.35 456.29 0 top
NOREF#3171  -  []  235.17 212.18 0 top
NOREF#3172  -  []  247.98 286.38 90 top
NOREF#3173  -  []  142.81 252.5 0 top
NOREF#3174  -  []  262.81 186.81 0 top
NOREF#3175  -  []  214.09 207.27 90 top
NOREF#3176  -  []  149.55 248.99 90 top
NOREF#3177  -  []  154.84 18.69 90 top
NOREF#3178  -  []  161.12 188.11 90 top
NOREF#3179  -  []  152.51 235.77 0 top
NOREF#3180  -  []  187.03 171.4 0 top
NOREF#3181  -  []  166.32 202.32 0 top
NOREF#3182  -  []  151.73 232.54 0 top
NOREF#3183  -  []  220.83 201.22 90 top
NOREF#3184  -  []  178.35 269.04 0 top
NOREF#3185  -  []  242.26 176.17 90 top
NOREF#3186  -  []  188.32 198.18 0 top
NOREF#3187  -  []  213.64 299.09 0 top
NOREF#3188  -  []  196.02 192.78 0 top
NOREF#3189  -  []  152.63 173.69 0 top
NOREF#3190  -  []  268.32 198.18 0 top
NOREF#3191  -  []  133.45 184.35 0 top
NOREF#3192  -  []  249.52 272.86 90 top
NOREF#3193  -  []  205.04 233.3 90 top
NOREF#3194  -  []  225.61 192.78 0 top
NOREF#3195  -  []  150.6 233.69 90 top
NOREF#3196  -  []  268.78 184.35 0 top
NOREF#3197  -  []  216.55 194.49 90 top
NOREF#3198  -  []  155.05 223.39 0 top
NOREF#3199  -  []  186.7 237.02 90 top
NOREF#3200  -  []  289.52 212.86 90 top
NOREF#3201  -  []  249.52 260.42 90 top
NOREF#3202  -  []  157.25 191.93 0 top
NOREF#3203  -  []  204.64 181.15 90 top
NOREF#3204  -  []  187.3 226.19 0 top
NOREF#3205  -  []  201.75 214.76 0 top
NOREF#3206  -  []  231.19 218.07 0 top
NOREF#3207  -  []  91.03 148.19 0 top
NOREF#3208  -  []  279.27 207.82 90 top
NOREF#3209  -  []  273.18 271.85 90 top
NOREF#3210  -  []  152.72 247.68 0 top
NOREF#3211  -  []  189.12 256.43 90 top
NOREF#3212  -  []  260.95 266.12 90 top
NOREF#3213  -  []  224.16 185.63 90 top
NOREF#3214  -  []  150.97 179.57 90 top
NOREF#3215  -  []  106.83 127.87 90 top
NOREF#3216  -  []  154.63 286.99 0 top
NOREF#3217  -  []  132.55 190.49 90 top
NOREF#3218  -  []  192.25 222.59 0 top
NOREF#3219  -  []  229.72 221.62 0 top
NOREF#3220  -  []  238.91 232.21 90 top
NOREF#3221  -  []  237.5 245.31 90 top
NOREF#3222  -  []  95.35 456.29 90 top
NOREF#3223  -  []  267.43 224.11 0 top
NOREF#3224  -  []  157.74 166.36 90 top
NOREF#3225  -  []  235.15 236.17 90 top
NOREF#3226  -  []  252.64 264.47 0 top
NOREF#3227  -  []  283.97 204.45 90 top
NOREF#3228  -  []  148.32 242.05 0 top
NOREF#3229  -  []  178.83 232.23 0 top
NOREF#3230  -  []  192.25 272.17 0 top
NOREF#3231  -  []  233.6 226.96 0 top
NOREF#3232  -  []  199.4 205.9 0 top
NOREF#3233  -  []  277.25 196.75 0 top
NOREF#3234  -  []  302.26 14.59 90 top
NOREF#3235  -  []  140.04 265.53 90 top
NOREF#3236  -  []  191.19 223.92 0 top
NOREF#3237  -  []  156.45 187.71 0 top
NOREF#3238  -  []  233.18 282.26 90 top
NOREF#3239  -  []  236.52 216.55 0 top
NOREF#3240  -  []  235.26 83.81 0 top
NOREF#3241  -  []  207.98 226.38 90 top
NOREF#3242  -  []  220.83 261.22 90 top
NOREF#3243  -  []  226.16 260.17 90 top
NOREF#3244  -  []  274.39 226.59 90 top
NOREF#3245  -  []  153.83 232.21 90 top
NOREF#3246  -  []  188.95 266.89 0 top
NOREF#3247  -  []  276.57 185.63 90 top
NOREF#3248  -  []  248.42 264.78 90 top
NOREF#3249  -  []  140.83 201.22 90 top
NOREF#3250  -  []  271.11 200.17 90 top
NOREF#3251  -  []  279.27 204.78 90 top
NOREF#3252  -  []  139.49 266.31 90 top
NOREF#3253  -  []  268.44 257.85 90 top
NOREF#3254  -  []  134.51 263.76 0 top
NOREF#3255  -  []  214.07 270.89 90 top
NOREF#3256  -  []  186.01 244.91 90 top
NOREF#3257  -  []  148.32 185.63 90 top
NOREF#3258  -  []  294.09 200.42 90 top
NOREF#3259  -  []  182.81 252.78 0 top
NOREF#3260  -  []  179.08 263.76 0 top
NOREF#3261  -  []  248.54 205.9 0 top
NOREF#3262  -  []  146.96 256.43 90 top
NOREF#3263  -  []  182.81 246.81 0 top
NOREF#3264  -  []  135.15 268.04 90 top
NOREF#3265  -  []  157.28 264.37 0 top
NOREF#3266  -  []  185.09 257.49 90 top
NOREF#3267  -  []  225.41 286.99 90 top
NOREF#3268  -  []  157.5 245.31 90 top
NOREF#3269  -  []  245.04 293.3 90 top
NOREF#3270  -  []  290.89 206.13 0 top
NOREF#3271  -  []  278.45 14.59 90 top
NOREF#3272  -  []  228.35 277.95 90 top
NOREF#3273  -  []  195.96 168.6 90 top
NOREF#3274  -  []  227.8 264.99 90 top
NOREF#3275  -  []  276.7 181.72 90 top
NOREF#3276  -  []  178.35 211.84 0 top
NOREF#3277  -  []  190.6 233.69 0 top
NOREF#3278  -  []  214.04 210.63 90 top
NOREF#3279  -  []  208.42 267.82 90 top
NOREF#3280  -  []  188.32 242.05 0 top
NOREF#3281  -  []  239.27 261.77 0 top
NOREF#3282  -  []  281.75 212.22 0 top
NOREF#3283  -  []  133.95 281.02 90 top
NOREF#3284  -  []  190.41 168.7 90 top
NOREF#3285  -  []  258.35 264.47 0 top
NOREF#3286  -  []  148.44 193.03 90 top
NOREF#3287  -  []  168.54 267.5 90 top
NOREF#3288  -  []  279.4 212 0 top
NOREF#3289  -  []  186.01 250.88 90 top
NOREF#3290  -  []  241.12 188.11 90 top
NOREF#3291  -  []  155.17 212.18 90 top
NOREF#3292  -  []  119.48 396.29 0 top
NOREF#3293  -  []  192.25 212.18 0 top
NOREF#3294  -  []  222.03 229.03 90 top
NOREF#3295  -  []  233.98 238.07 0 top
NOREF#3296  -  []  239.27 271.67 0 top
NOREF#3297  -  []  230.6 173.69 0 top
NOREF#3298  -  []  258.35 209.04 0 top
NOREF#3299  -  []  262.81 257.6 0 top
NOREF#3300  -  []  276.84 227.33 0 top
NOREF#3301  -  []  129.49 266.31 0 top
NOREF#3302  -  []  142.81 192.78 0 top
NOREF#3303  -  []  288.39 456.29 0 top
NOREF#3304  -  []  236.8 214.65 90 top
NOREF#3305  -  []  266.96 196.43 90 top
NOREF#3306  -  []  222.03 289.03 90 top
NOREF#3307  -  []  227.05 209.24 0 top
NOREF#3308  -  []  186.96 196.43 90 top
NOREF#3309  -  []  282.26 236.17 90 top
NOREF#3310  -  []  148.19 187.71 0 top
NOREF#3311  -  []  196.8 280.49 90 top
NOREF#3312  -  []  145.42 286.99 90 top
NOREF#3313  -  []  199.4 267.5 90 top
NOREF#3314  -  []  197.25 180.62 0 top
NOREF#3315  -  []  236.1 220.99 90 top
NOREF#3316  -  []  293.02 392.33 90 top
NOREF#3317  -  []  188.95 206.89 0 top
NOREF#3318  -  []  237.25 251.93 0 top
NOREF#3319  -  []  202.57 231.95 0 top
NOREF#3320  -  []  266.43 296.46 90 top
NOREF#3321  -  []  226.43 296.46 90 top
NOREF#3322  -  []  230.77 273.37 90 top
NOREF#3323  -  []  231.79 256.75 0 top
NOREF#3324  -  []  212.87 227.4 90 top
NOREF#3325  -  []  184.16 251.6 90 top
NOREF#3326  -  []  218.97 271.91 90 top
NOREF#3327  -  []  236.1 216.42 90 top
NOREF#3328  -  []  209.55 237.49 90 top
NOREF#3329  -  []  242.2 178.35 0 top
NOREF#3330  -  []  229.84 224.11 90 top
NOREF#3331  -  []  203.97 262.09 0 top
NOREF#3332  -  []  170.02 214.45 0 top
NOREF#3333  -  []  268.95 206.89 0 top
NOREF#3334  -  []  178.95 206.12 0 top
NOREF#3335  -  []  149.12 240.3 90 top
NOREF#3336  -  []  227.43 284.11 0 top
NOREF#3337  -  []  209.55 237.49 0 top
NOREF#3338  -  []  249.52 204.23 90 top
NOREF#3339  -  []  284.95 207.27 90 top
NOREF#3340  -  []  267.03 171.4 0 top
NOREF#3341  -  []  146.83 191.93 0 top
NOREF#3342  -  []  158.04 228.3 0 top
NOREF#3343  -  []  140.43 224.38 90 top
NOREF#3344  -  []  261.55 267.14 90 top
NOREF#3345  -  []  271.24 257.85 90 top
NOREF#3346  -  []  236.57 193.35 0 top
NOREF#3347  -  []  189.72 275.77 0 top
NOREF#3348  -  []  272.63 233.69 90 top
NOREF#3349  -  []  138.35 211.84 0 top
NOREF#3350  -  []  139.72 273.6 90 top
NOREF#3351  -  []  197.71 233.69 0 top
NOREF#3352  -  []  157.92 252.5 90 top
NOREF#3353  -  []  128.46 18.69 0 top
NOREF#3354  -  []  147.43 278.27 0 top
NOREF#3355  -  []  218.83 232.23 0 top
NOREF#3356  -  []  216.98 205.11 90 top
NOREF#3357  -  []  204.44 292.28 90 top
NOREF#3358  -  []  237.5 185.31 90 top
NOREF#3359  -  []  274.07 256.43 90 top
NOREF#3360  -  []  281.41 167.9 90 top
NOREF#3361  -  []  156.45 247.71 0 top
NOREF#3362  -  []  228.32 245.63 0 top
NOREF#3363  -  []  229.84 273.7 90 top
NOREF#3364  -  []  170.89 206.13 0 top
NOREF#3365  -  []  176.74 456.29 0 top
NOREF#3366  -  []  274.07 251.6 90 top
NOREF#3367  -  []  166.32 206.13 0 top
NOREF#3368  -  []  198.47 82.65 0 top
NOREF#3369  -  []  206.32 262.32 0 top
NOREF#3370  -  []  275.17 281.32 90 top
NOREF#3371  -  []  272.51 235.77 0 top
NOREF#3372  -  []  195.05 223.39 0 top
NOREF#3373  -  []  203.97 208.95 0 top
NOREF#3374  -  []  149.78 228.3 0 top
NOREF#3375  -  []  273.6 286.96 0 top
NOREF#3376  -  []  261.85 306.46 0 top
NOREF#3377  -  []  176.38 264.09 90 top
NOREF#3378  -  []  273.98 238.07 0 top
NOREF#3379  -  []  175.84 262.57 90 top
NOREF#3380  -  []  181.55 267.14 90 top
NOREF#3381  -  []  173.62 289.09 90 top
NOREF#3382  -  []  232.63 173.69 90 top
NOREF#3383  -  []  206.32 266.13 0 top
NOREF#3384  -  []  193.83 172.21 90 top
NOREF#3385  -  []  209.52 260.42 90 top
NOREF#3386  -  []  88.44 107.76 0 top
NOREF#3387  -  []  191.11 260.17 90 top
NOREF#3388  -  []  203.84 270.87 90 top
NOREF#3389  -  []  149.24 185.31 90 top
NOREF#3390  -  []  149.84 224.11 90 top
NOREF#3391  -  []  176.26 263.76 90 top
NOREF#3392  -  []  243.04 236.5 90 top
NOREF#3393  -  []  267.43 278.27 90 top
NOREF#3394  -  []  141.85 246.47 0 top
NOREF#3395  -  []  226.7 237.02 90 top
NOREF#3396  -  []  244.95 200.42 90 top
NOREF#3397  -  []  268.32 258.18 0 top
NOREF#3398  -  []  89.76 144.42 90 top
NOREF#3399  -  []  271.71 231.3 0 top
NOREF#3400  -  []  174.43 232.23 0 top
NOREF#3401  -  []  243.97 212 0 top
NOREF#3402  -  []  189.84 284.11 0 top
NOREF#3403  -  []  239.72 214.65 90 top
NOREF#3404  -  []  123.4 236.38 0 top
NOREF#3405  -  []  139.55 294.49 0 top
NOREF#3406  -  []  138.95 264.09 0 top
NOREF#3407  -  []  157.59 175.77 0 top
NOREF#3408  -  []  268.81 250.88 90 top
NOREF#3409  -  []  286.32 214.76 0 top
NOREF#3410  -  []  201.41 227.9 90 top
NOREF#3411  -  []  154.86 454.29 90 top
NOREF#3412  -  []  271.18 239.15 0 top
NOREF#3413  -  []  188.81 190.88 90 top
NOREF#3414  -  []  243.84 264.78 90 top
NOREF#3415  -  []  186.01 190.88 90 top
NOREF#3416  -  []  283.97 264.45 90 top
NOREF#3417  -  []  231.91 191.6 90 top
NOREF#3418  -  []  204.44 232.28 90 top
NOREF#3419  -  []  203.84 208.62 0 top
NOREF#3420  -  []  239.27 207.82 90 top
NOREF#3421  -  []  276.38 241.15 90 top
NOREF#3422  -  []  203.84 210.87 90 top
NOREF#3423  -  []  196.81 172.54 0 top
NOREF#3424  -  []  197.59 235.77 0 top
NOREF#3425  -  []  148.81 190.88 90 top
NOREF#3426  -  []  271.73 172.54 0 top
NOREF#3427  -  []  253.24 261.55 0 top
NOREF#3428  -  []  181.85 246.47 0 top
NOREF#3429  -  []  245.38 226.23 0 top
NOREF#3430  -  []  218.35 269.04 0 top
NOREF#3431  -  []  239.27 273.41 90 top
NOREF#3432  -  []  143.61 396.29 0 top
NOREF#3433  -  []  242.57 291.95 0 top
NOREF#3434  -  []  122.57 291.95 0 top
NOREF#3435  -  []  155.15 236.17 90 top
NOREF#3436  -  []  232.66 226.35 90 top
NOREF#3437  -  []  239.22 179.57 90 top
NOREF#3438  -  []  207.98 286.38 90 top
NOREF#3439  -  []  187.99 238.35 0 top
NOREF#3440  -  []  174.38 204.09 0 top
NOREF#3441  -  []  156.1 271.85 90 top
NOREF#3442  -  []  165.04 293.3 90 top
NOREF#3443  -  []  214.51 263.76 0 top
NOREF#3444  -  []  190.88 228.6 90 top
NOREF#3445  -  []  233.56 173.37 90 top
NOREF#3446  -  []  254.51 263.76 0 top
NOREF#3447  -  []  157.18 236.17 90 top
NOREF#3448  -  []  124.32 231.95 90 top
NOREF#3449  -  []  195.17 272.17 0 top
NOREF#3450  -  []  180.95 206.12 90 top
NOREF#3451  -  []  202.26 236.17 90 top
NOREF#3452  -  []  259.72 213.6 90 top
NOREF#3453  -  []  237.59 235.77 0 top
NOREF#3454  -  []  147.45 209.24 0 top
NOREF#3455  -  []  227.3 280.35 0 top
NOREF#3456  -  []  148.99 191.93 0 top
NOREF#3457  -  []  156.1 211.85 90 top
NOREF#3458  -  []  263.36 258.18 0 top
NOREF#3459  -  []  173.24 261.55 0 top
NOREF#3460  -  []  267.99 178.35 0 top
NOREF#3461  -  []  204.95 200.42 90 top
NOREF#3462  -  []  236.57 182.05 0 top
NOREF#3463  -  []  246.32 212.22 0 top
NOREF#3464  -  []  268.44 241.72 90 top
NOREF#3465  -  []  256.38 204.09 90 top
NOREF#3466  -  []  233.39 197.85 90 top
NOREF#3467  -  []  153.39 193.03 90 top
NOREF#3468  -  []  267.05 209.24 0 top
NOREF#3469  -  []  279.22 239.57 90 top
NOREF#3470  -  []  188.32 258.18 0 top
NOREF#3471  -  []  212.64 264.47 0 top
NOREF#3472  -  []  219.08 263.76 0 top
NOREF#3473  -  []  271.46 167 0 top
NOREF#3474  -  []  243.97 268.95 0 top
NOREF#3475  -  []  170.92 291.95 90 top
NOREF#3476  -  []  276.02 192.78 0 top
NOREF#3477  -  []  249.52 264.23 90 top
NOREF#3478  -  []  193.27 253.35 0 top
NOREF#3479  -  []  254.04 210.63 90 top
NOREF#3480  -  []  181.55 202.57 90 top
NOREF#3481  -  []  131.26 184.35 0 top
NOREF#3482  -  []  204.95 272.86 90 top
NOREF#3483  -  []  152.46 252.5 90 top
NOREF#3484  -  []  189.84 273.7 0 top
NOREF#3485  -  []  180.59 244.98 90 top
NOREF#3486  -  []  0 382.27 0 top
NOREF#3487  -  []  284.64 181.15 90 top
NOREF#3488  -  []  283.97 212 0 top
NOREF#3489  -  []  194.78 236.5 90 top
NOREF#3490  -  []  250.92 291.95 90 top
NOREF#3491  -  []  276.1 211.85 90 top
NOREF#3492  -  []  221.59 294.14 0 top
NOREF#3493  -  []  235.58 262.67 90 top
NOREF#3494  -  []  294.09 204.23 90 top
NOREF#3495  -  []  141.55 202.57 90 top
NOREF#3496  -  []  201.75 202.32 0 top
NOREF#3497  -  []  258.35 267.01 0 top
NOREF#3498  -  []  266.69 283.04 90 top
NOREF#3499  -  []  235.49 168.7 90 top
NOREF#3500  -  []  237.71 173.69 0 top
NOREF#3501  -  []  236.1 211.85 90 top
NOREF#3502  -  []  219.55 294.49 0 top
NOREF#3503  -  []  259.08 261.22 0 top
NOREF#3504  -  []  288.54 265.9 0 top
NOREF#3505  -  []  187.3 280.35 0 top
NOREF#3506  -  []  138.75 457.2 0 top
NOREF#3507  -  []  197.71 172.86 0 top
NOREF#3508  -  []  232.25 222.59 0 top
NOREF#3509  -  []  203.97 264.45 90 top
NOREF#3510  -  []  234.78 176.5 90 top
NOREF#3511  -  []  193.98 238.07 0 top
NOREF#3512  -  []  106.68 128.02 0 top
NOREF#3513  -  []  288.42 264.78 90 top
NOREF#3514  -  []  273.18 222.26 90 top
NOREF#3515  -  []  153.27 253.35 0 top
NOREF#3516  -  []  162.85 237.22 0 top
NOREF#3517  -  []  233.98 178.07 0 top
NOREF#3518  -  []  114.55 316.49 0 top
NOREF#3519  -  []  270.6 233.69 0 top
NOREF#3520  -  []  258.95 204.09 0 top
NOREF#3521  -  []  202.26 176.17 90 top
NOREF#3522  -  []  197.74 226.35 90 top
NOREF#3523  -  []  140.83 203.76 90 top
NOREF#3524  -  []  188.81 195.7 90 top
NOREF#3525  -  []  273.98 178.07 0 top
NOREF#3526  -  []  119.46 18.69 90 top
NOREF#3527  -  []  194.39 216.17 90 top
NOREF#3528  -  []  203.97 213.09 90 top
NOREF#3529  -  []  244.95 207.27 90 top
NOREF#3530  -  []  180.95 208.91 90 top
NOREF#3531  -  []  204.95 207.27 90 top
NOREF#3532  -  []  169.52 272.86 90 top
NOREF#3533  -  []  192.13 274.25 0 top
NOREF#3534  -  []  129.49 220.89 0 top
NOREF#3535  -  []  209.55 237.49 0 top
NOREF#3536  -  []  281.75 206.13 0 top
NOREF#3537  -  []  146.83 256.75 0 top
NOREF#3538  -  []  226.01 255.7 90 top
NOREF#3539  -  []  277.04 244.35 0 top
NOREF#3540  -  []  187.8 209.99 0 top
NOREF#3541  -  []  143.61 456.29 90 top
NOREF#3542  -  []  140.95 204.09 90 top
NOREF#3543  -  []  213.78 207.01 0 top
NOREF#3544  -  []  189.84 279.54 90 top
NOREF#3545  -  []  187.77 252.78 0 top
NOREF#3546  -  []  153.18 282.26 90 top
NOREF#3547  -  []  268.32 253.35 0 top
NOREF#3548  -  []  215.65 244.35 0 top
NOREF#3549  -  []  189.12 180.3 90 top
NOREF#3550  -  []  156.57 245.63 0 top
NOREF#3551  -  []  154.39 222.02 90 top
NOREF#3552  -  []  184.16 196.43 90 top
NOREF#3553  -  []  195.15 236.17 90 top
NOREF#3554  -  []  273.39 257.85 90 top
NOREF#3555  -  []  180.83 263.76 90 top
NOREF#3556  -  []  271.71 171.3 0 top
NOREF#3557  -  []  193.6 286.96 0 top
NOREF#3558  -  []  210.89 262.32 0 top
NOREF#3559  -  []  135.84 202.57 90 top
NOREF#3560  -  []  159.4 262.09 0 top
NOREF#3561  -  []  220.83 203.76 90 top
NOREF#3562  -  []  246.32 202.32 0 top
NOREF#3563  -  []  289.52 264.23 90 top
NOREF#3564  -  []  259.72 273.6 90 top
NOREF#3565  -  []  309.55 14.59 90 top
NOREF#3566  -  []  188.19 187.71 0 top
NOREF#3567  -  []  224.16 245.63 90 top
NOREF#3568  -  []  260.43 224.38 90 top
NOREF#3569  -  []  253.45 244.35 0 top
NOREF#3570  -  []  248.54 202.09 0 top
NOREF#3571  -  []  193.27 198.18 0 top
NOREF#3572  -  []  227.43 218.27 0 top
NOREF#3573  -  []  191.79 256.75 0 top
NOREF#3574  -  []  279.72 214.65 90 top
NOREF#3575  -  []  156.02 251.31 0 top
NOREF#3576  -  []  229.55 188.99 90 top
NOREF#3577  -  []  221.85 246.47 0 top
NOREF#3578  -  []  254.04 270.63 90 top
NOREF#3579  -  []  225.42 274.72 90 top
NOREF#3580  -  []  143.61 456.29 0 top
NOREF#3581  -  []  266.83 251.93 0 top
NOREF#3582  -  []  245.38 286.23 0 top
NOREF#3583  -  []  258.97 271.91 90 top
NOREF#3584  -  []  272.13 220.09 0 top
NOREF#3585  -  []  190.6 173.69 0 top
NOREF#3586  -  []  268.99 240.62 0 top
NOREF#3587  -  []  197.25 196.75 0 top
NOREF#3588  -  []  237.92 250.01 0 top
NOREF#3589  -  []  228.44 181.72 90 top
NOREF#3590  -  []  237.71 233.69 0 top
NOREF#3591  -  []  195.17 281.32 0 top
NOREF#3592  -  []  168.42 261.77 0 top
NOREF#3593  -  []  277.25 240.62 0 top
NOREF#3594  -  []  312.52 396.29 0 top
NOREF#3595  -  []  138.97 211.91 90 top
NOREF#3596  -  []  174.09 200.42 90 top
NOREF#3597  -  []  227.99 238.35 0 top
NOREF#3598  -  []  254.07 210.89 90 top
NOREF#3599  -  []  146.16 200.17 90 top
NOREF#3600  -  []  169.17 291.95 0 top
NOREF#3601  -  []  279.72 219.22 90 top
NOREF#3602  -  []  266.16 258.18 0 top
NOREF#3603  -  []  146.16 258.18 0 top
NOREF#3604  -  []  239.27 265.58 0 top
NOREF#3605  -  []  191.46 167 0 top
NOREF#3606  -  []  234.39 216.17 90 top
NOREF#3607  -  []  264.24 18.69 0 top
NOREF#3608  -  []  169.52 264.23 90 top
NOREF#3609  -  []  144.16 196.43 90 top
NOREF#3610  -  []  275.05 283.39 0 top
NOREF#3611  -  []  276.45 247.71 0 top
NOREF#3612  -  []  275.49 228.7 90 top
NOREF#3613  -  []  195.49 168.7 90 top
NOREF#3614  -  []  251.05 185.49 90 top
NOREF#3615  -  []  239.27 201.77 0 top
NOREF#3616  -  []  221.6 17.15 90 top
NOREF#3617  -  []  159.27 265.58 0 top
NOREF#3618  -  []  231.18 179.15 0 top
NOREF#3619  -  []  203.97 267.5 90 top
NOREF#3620  -  []  210.89 209.17 0 top
NOREF#3621  -  []  196.1 220.99 90 top
NOREF#3622  -  []  147.9 265.84 90 top
NOREF#3623  -  []  230.97 255.7 90 top
NOREF#3624  -  []  187.99 178.35 0 top
NOREF#3625  -  []  265.41 273.02 90 top
NOREF#3626  -  []  153.27 193.35 0 top
NOREF#3627  -  []  318.12 17.15 90 top
NOREF#3628  -  []  255.84 202.57 90 top
NOREF#3629  -  []  131.22 294.89 90 top
NOREF#3630  -  []  173.65 239.15 0 top
NOREF#3631  -  []  144.16 191.6 90 top
NOREF#3632  -  []  134.43 292.23 0 top
NOREF#3633  -  []  206.32 202.32 0 top
NOREF#3634  -  []  273.03 232.1 0 top
NOREF#3635  -  []  196.57 185.63 90 top
NOREF#3636  -  []  186.43 236.47 90 top
NOREF#3637  -  []  189.84 279.54 0 top
NOREF#3638  -  []  239.44 179.15 0 top
NOREF#3639  -  []  243.04 176.5 90 top
NOREF#3640  -  []  156.81 232.54 0 top
NOREF#3641  -  []  149.29 285.22 0 top
NOREF#3642  -  []  155.17 272.17 90 top
NOREF#3643  -  []  194.33 267.37 90 top
NOREF#3644  -  []  243.97 200.64 90 top
